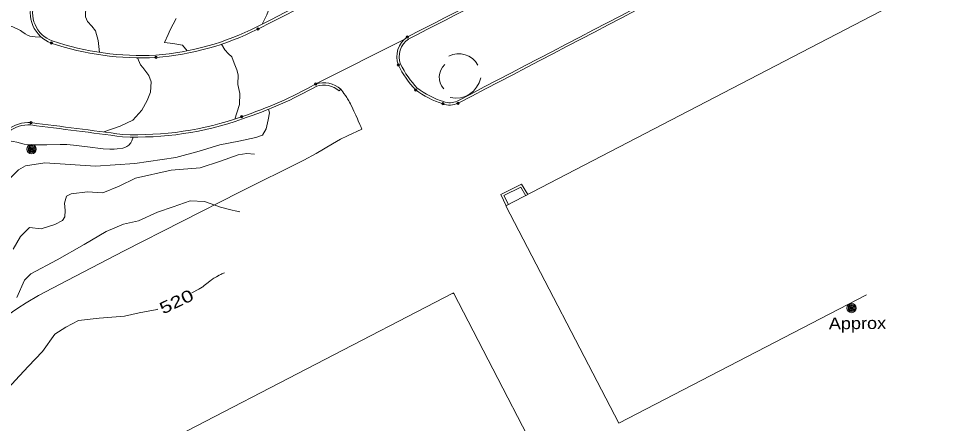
# Model space of a CAD drawing. Extents: x 2361284 to 2366480, y 6976556 to 6985346.
# Drawn here: x 2365034.3 to 2365416.7, y 6979380.5 to 6979545.4 of the extents above; entities that cross this region are included whole.
import ezdxf
from ezdxf.enums import TextEntityAlignment as Align

# ---------------------------------------------------------------- set-up
doc = ezdxf.new("R2010")
doc.units = 0
doc.header["$LTSCALE"] = 1.9
doc.header["$PDMODE"] = 32
doc.header["$PDSIZE"] = 0.95
for name, color, linetype, lineweight in [('12', 7, 'Continuous', 13), ('13', 7, 'Continuous', 13), ('16', 7, 'Continuous', 13), ('3', 7, 'Continuous', 13), ('4', 7, 'Continuous', 13), ('7', 7, 'Continuous', 13)]:
    doc.layers.add(name, color=color, linetype=linetype, lineweight=lineweight)

msp = doc.modelspace()

# ---------------------------------------------------------------- linework, layer by layer
at = {"layer": '12'}
for points in [[(2365121.308, 6979576.326), (2365119.928, 6979575.303), (2365111.99, 6979573.897), (2365105.729, 6979571.798), (2365096.755, 6979569.032), (2365089.949, 6979567.538), (2365082.529, 6979564.398), (2365074.493, 6979560.661), (2365070.51, 6979556.862), (2365063.341, 6979553.584), (2365061.642, 6979550.732), (2365061.489, 6979546.204), (2365062.379, 6979544.334), (2365064.177, 6979542.401), (2365065.576, 6979540.435), (2365066.723, 6979536.506), (2365067.199, 6979531.72)], [(2365043.569, 6979537.876), (2365040.968, 6979538.031), (2365038.905, 6979538.365), (2365037.901, 6979538.691), (2365036.887, 6979539.274), (2365035.656, 6979540.226), (2365035.002, 6979540.644), (2365031.989, 6979542.103), (2365030.403, 6979542.72), (2365028.393, 6979543.31), (2365027.374, 6979543.516), (2365025.84, 6979543.707), (2365023.562, 6979543.705), (2365021.562, 6979543.414), (2365020.569, 6979543.173), (2365019.094, 6979542.694), (2365016.941, 6979541.712), (2365014.212, 6979540.026), (2365010.772, 6979537.666), (2365008.98, 6979536.597), (2365003.418, 6979533.731), (2365000.558, 6979532.436)], [(2365118.196, 6979441.849), (2365117.222, 6979441.395), (2365116.743, 6979441.159), (2365116.031, 6979440.794), (2365114.982, 6979440.22), (2365113.95, 6979439.612), (2365113.44, 6979439.294), (2365112.79, 6979438.854), (2365112.368, 6979438.544), (2365111.546, 6979437.894), (2365109.924, 6979436.567), (2365109.372, 6979436.143), (2365109.091, 6979435.939), (2365108.517, 6979435.55), (2365108.222, 6979435.367), (2365107.769, 6979435.11), (2365104.893, 6979433.623)], [(2365090.866, 6979426.919), (2365090.797, 6979426.888), (2365083.489, 6979425.51), (2365077.442, 6979424.101), (2365067.089, 6979423.363), (2365058.669, 6979422.293), (2365053.493, 6979419.673), (2365048.99, 6979416.8), (2365044.078, 6979409.723), (2365038.145, 6979403.617), (2365033.068, 6979398.048), (2365027.257, 6979391.763), (2365022.139, 6979387.334), (2365014.301, 6979381.889), (2365009.957, 6979377.046), (2365004.624, 6979368.746), (2365002.393, 6979364.705), (2364999.96, 6979360.762), (2364997.599, 6979357.698), (2364995.39, 6979356.567), (2364991.199, 6979356.597)]]:
    msp.add_lwpolyline(points, dxfattribs=at)
at = {"layer": '13'}
for points in [[(2365152.005, 6979575.758), (2365150.833, 6979574.887), (2365149.529, 6979572.194), (2365149.399, 6979570.013), (2365148.154, 6979566.352), (2365146.516, 6979561.986), (2365144.395, 6979558.916), (2365138.73, 6979556.151), (2365137.23, 6979552.936), (2365136.695, 6979550.371), (2365135.456, 6979547.079), (2365133.633, 6979543.182)], [(2365098.493, 6979545.5), (2365096.133, 6979540.885), (2365095.231, 6979538.946), (2365093.821, 6979535.773), (2365097.107, 6979535.344), (2365101.064, 6979534.592), (2365102.985, 6979532.33)], [(2365116.96, 6979535.013), (2365118.341, 6979532.746), (2365119.888, 6979531.131), (2365121.18, 6979529.893), (2365122.224, 6979527.283), (2365123.24, 6979524.562), (2365123.819, 6979522.558), (2365123.727, 6979518.586), (2365124.522, 6979514.914), (2365124.295, 6979510.432), (2365123.207, 6979507.011), (2365122.491, 6979504.534)], [(2365082.781, 6979529.488), (2365083.938, 6979526.669), (2365084.959, 6979525.508), (2365087.42, 6979522.271), (2365088.274, 6979519.749), (2365088.124, 6979515.498), (2365086.757, 6979512.024), (2365084.523, 6979508.203), (2365080.903, 6979504.039), (2365075.755, 6979501.66), (2365068.998, 6979499.245)], [(2365136.183, 6979508.484), (2365136.586, 6979507.058), (2365136.033, 6979504.213), (2365135.218, 6979500.525), (2365133.793, 6979497.911), (2365131.011, 6979497.055), (2365124.137, 6979495.429), (2365116.349, 6979494.055), (2365107.943, 6979491.484), (2365098.369, 6979488.793), (2365081.731, 6979486.335), (2365065.689, 6979485.362), (2365045.006, 6979486.656), (2365037.078, 6979485.43), (2365034.204, 6979483.851), (2365029.694, 6979479.341), (2365027.14, 6979475.546), (2365024.67, 6979472.403), (2365023.426, 6979471.618), (2365020.525, 6979471.793)], [(2365080.978, 6979497.149), (2365080.476, 6979495.604), (2365080.07, 6979494.86), (2365079.172, 6979493.838), (2365078.451, 6979493.323), (2365077.929, 6979493.054), (2365076.81, 6979492.699), (2365074.425, 6979492.327), (2365073.23, 6979492.224), (2365071.438, 6979492.176), (2365068.763, 6979492.353), (2365062.355, 6979493.172), (2365056.73, 6979493.923), (2365053.905, 6979494.142), (2365051.202, 6979494.17), (2365045.795, 6979494.064), (2365038.767, 6979493.948), (2365038.014, 6979493.995), (2365036.527, 6979494.244), (2365033.583, 6979495.021), (2365032.103, 6979495.354), (2365027.334, 6979496.179)], [(2365130.427, 6979490.178), (2365127.365, 6979490.429), (2365123.81, 6979489.885), (2365116.552, 6979487.396), (2365108.369, 6979484.608), (2365096.548, 6979483.605), (2365081.958, 6979480.368), (2365075.227, 6979477.203), (2365068.583, 6979474.45), (2365062.439, 6979474.852), (2365055.697, 6979474.028), (2365053.866, 6979473.03), (2365052.983, 6979470.202), (2365053.262, 6979467.203), (2365053.177, 6979464.572), (2365052.161, 6979463.206), (2365049.034, 6979461.553), (2365043.482, 6979459.74), (2365038.727, 6979460.265), (2365035.091, 6979456.62), (2365032.12, 6979451.492)], [(2365124.491, 6979466.63), (2365122.587, 6979467.102), (2365121.334, 6979467.41), (2365116.612, 6979468.516), (2365110.029, 6979470.914), (2365104.236, 6979471.139), (2365097.33, 6979468.722), (2365090.96, 6979466.502), (2365083.193, 6979462.938), (2365077.096, 6979461.58), (2365069.933, 6979458.691), (2365060.984, 6979453.307), (2365050.022, 6979447.081), (2365039.266, 6979441.409), (2365036.668, 6979438.747), (2365033.508, 6979431.714)]]:
    msp.add_lwpolyline(points, dxfattribs=at)
at = {"layer": '16'}
for centre, radius, start, end in [((2365213.838, 6979522.424), 8.721, 28.11827, 118.11827), ((2365212.795, 6979521.562), 6.97, 132.27574, 222.27574), ((2365212.504, 6979523.488), 10.46, 257.76462, 347.76462)]:
    msp.add_arc(centre, radius, start, end, dxfattribs=at)
at = {"layer": '3'}
for p, q in [((2365131.46, 6979542.083), (2365131.458, 6979542.082)), ((2365047.95, 6979536.406), (2365047.93, 6979536.413)), ((2365155.446, 6979518.818), (2365191.575, 6979537.003)), ((2365193.204, 6979537.089), (2365193.301, 6979537.147)), ((2365090.267, 6979530.608), (2365090.246, 6979530.607)), ((2365190.06, 6979526.875), (2365190.025, 6979526.955)), ((2365155.733, 6979517.902), (2365155.915, 6979517.98)), ((2365165.687, 6979516.705), (2365165.064, 6979515.979)), ((2365196.862, 6979517.081), (2365196.736, 6979517.194)), ((2365213.12, 6979511.851), (2365213.081, 6979511.831)), ((2365207.584, 6979511.636), (2365207.626, 6979511.622)), ((2365125.545, 6979504.559), (2365125.562, 6979504.565)), ((2365039.209, 6979502.111), (2365039.261, 6979502.106)), ((2365076.696, 6979497.269), (2365076.613, 6979497.277)), ((2365076.738, 6979498.229), (2365076.738, 6979498.228))]:
    msp.add_line(p, q, dxfattribs=at)
for points in [[(2365174.243, 6979500.326), (2365173.789, 6979501.512), (2365173.474, 6979502.297), (2365172.818, 6979503.853), (2365172.478, 6979504.626), (2365171.778, 6979506.164), (2365171.056, 6979507.693), (2365170.564, 6979508.71), (2365169.564, 6979510.742), (2365169.201, 6979511.446), (2365168.948, 6979511.906), (2365168.417, 6979512.808), (2365168.141, 6979513.251), (2365167.566, 6979514.126), (2365166.963, 6979514.989), (2365166.548, 6979515.561), (2365165.687, 6979516.705)], [(2365027.381, 6979422.865), (2365033.957, 6979427.349), (2365037.3, 6979429.496), (2365042.451, 6979432.489), (2365054.047, 6979438.654), (2365077.349, 6979450.752), (2365124.324, 6979474.72), (2365150.592, 6979487.69), (2365155.633, 6979490.467), (2365162.234, 6979494.395), (2365165.591, 6979496.264), (2365168.435, 6979497.7), (2365174.243, 6979500.326)], [(2365241.949, 6979473.748), (2365239.419, 6979477.985), (2365230.939, 6979473.794), (2365233.183, 6979469.184)], [(2365241.124, 6979473.261), (2365239.051, 6979476.731), (2365232.223, 6979473.356), (2365234.049, 6979469.603)]]:
    msp.add_lwpolyline(points, dxfattribs=at)
for centre, radius, start, end in [((2362239.81, 6985246.954), 6395.873, 296.87924, 298.72114), ((2362239.81, 6985246.954), 6396.833, 296.87924, 298.72114), ((2352739.774, 7003491.687), 27029.926, 297.48154, 297.90714), ((2352739.774, 7003491.687), 27030.886, 297.48154, 297.90714), ((2355215.381, 6999015.249), 21884.095, 297.12411, 297.48186), ((2355215.381, 6999015.248), 21885.055, 297.12411, 297.48186), ((2365052.083, 6979547.764), 13.047, 156.32244, 250.00279), ((2365052.083, 6979547.764), 12.087, 156.32244, 250.00279), ((2365081.847, 6979640.513), 110.227, 274.37023, 296.74983), ((2365081.847, 6979640.513), 111.187, 274.37023, 296.74983), ((2365084.144, 6979643.24), 113.758, 251.2736, 273.11213), ((2365084.144, 6979643.24), 112.798, 251.2736, 273.11213), ((2365198.106, 6979529.984), 9.585, 123.85297, 201.12604), ((2365198.106, 6979529.984), 8.625, 123.85297, 201.12604), ((2365226.965, 6979545.229), 42.173, 206.32224, 223.07883), ((2365226.965, 6979545.229), 41.213, 206.32223, 223.07883), ((2365069.97, 6979671.391), 174.884, 288.42379, 299.25883), ((2365069.97, 6979671.391), 175.845, 288.4238, 299.25883), ((2365158.667, 6979508.554), 10.758, 49.26394, 107.41953), ((2365158.667, 6979508.554), 9.798, 49.26395, 107.41954), ((2365218.513, 6979546.335), 37.339, 233.2297, 252.51837), ((2365218.513, 6979546.335), 36.379, 233.22969, 252.51837), ((2365210.097, 6979518.371), 7.187, 249.89048, 294.87497), ((2365210.097, 6979518.371), 8.147, 249.89048, 294.87497), ((2365082.368, 6979626.578), 129.433, 267.48831, 289.49466), ((2365082.368, 6979626.578), 128.472, 267.48831, 289.49466), ((2365038.33, 6979489.03), 14.069, 85.92585, 169.25954), ((2365038.33, 6979489.03), 13.109, 85.92585, 169.25954), ((2363839.649, 6970073.29), 9504.82, 82.52228, 82.74963), ((2363839.649, 6970073.29), 9505.78, 82.52228, 82.74963)]:
    msp.add_arc(centre, radius, start, end, dxfattribs=at)
for p in [(2365131.892, 6979541.225), (2365047.622, 6979535.504), (2365192.766, 6979537.944), (2365090.32, 6979529.649), (2365189.165, 6979526.529), (2365155.446, 6979518.818), (2365196.161, 6979516.425), (2365207.296, 6979510.721), (2365213.524, 6979510.98), (2365125.241, 6979505.47), (2365039.33, 6979503.063)]:
    msp.add_point(p, dxfattribs=at)
at = {"layer": '4'}
for centre, radius in [((2365039.583, 6979492.235), 1.9), ((2365039.583, 6979492.235), 1.442), ((2365039.583, 6979492.235), 0.539), ((2365039.583, 6979492.235), 0.192), ((2365373.997, 6979427.452), 1.9), ((2365373.997, 6979427.452), 1.442), ((2365373.997, 6979427.452), 0.539), ((2365373.997, 6979427.452), 0.192)]:
    msp.add_circle(centre, radius, dxfattribs=at)
for centre, start, end in [((2365039.583, 6979492.235), 152.21535, 163.46538), ((2365039.583, 6979492.235), 140.96646, 152.21649), ((2365039.583, 6979492.235), 129.71376, 140.96379), ((2365039.583, 6979492.235), 118.46406, 129.71409), ((2365039.583, 6979492.235), 107.21593, 118.46597), ((2365039.583, 6979492.235), 95.96582, 107.21585), ((2365039.583, 6979492.235), 84.71553, 95.96557), ((2365039.583, 6979492.235), 73.46552, 84.71555), ((2365039.583, 6979492.235), 62.21535, 73.46538), ((2365039.583, 6979492.235), 50.96397, 62.214), ((2365039.583, 6979492.235), 39.71588, 50.96591), ((2365039.583, 6979492.235), 28.46656, 39.7166), ((2365039.583, 6979492.235), 17.21479, 28.46483), ((2365039.583, 6979492.235), 174.71552, 185.96556), ((2365039.583, 6979492.235), 163.46611, 174.71615), ((2365039.583, 6979492.235), 185.96287, 197.21291), ((2365039.583, 6979492.235), 197.21479, 208.46483), ((2365039.583, 6979492.235), 208.46822, 219.71826), ((2365039.583, 6979492.235), 219.71376, 230.96379), ((2365039.583, 6979492.235), 230.96397, 242.214), ((2365039.583, 6979492.235), 242.21812, 253.46815), ((2365039.583, 6979492.235), 253.46258, 264.71261), ((2365039.583, 6979492.235), 264.71553, 275.96557), ((2365039.583, 6979492.235), 275.96582, 287.21585), ((2365039.583, 6979492.235), 287.21593, 298.46597), ((2365039.583, 6979492.235), 298.46406, 309.71409), ((2365039.583, 6979492.235), 309.71589, 320.96592), ((2365039.583, 6979492.235), 320.96646, 332.21649), ((2365039.583, 6979492.235), 332.21419, 343.46422), ((2365039.583, 6979492.235), 5.96345, 17.21348), ((2365039.583, 6979492.235), 343.46611, 354.71615), ((2365039.583, 6979492.235), 354.71553, 5.96557), ((2365373.997, 6979427.452), 163.46611, 174.71615), ((2365373.997, 6979427.452), 152.21535, 163.46538), ((2365373.997, 6979427.452), 140.96646, 152.21649), ((2365373.997, 6979427.452), 129.71376, 140.96379), ((2365373.997, 6979427.452), 118.46406, 129.71409), ((2365373.997, 6979427.452), 107.21593, 118.46597), ((2365373.997, 6979427.452), 95.96582, 107.21585), ((2365373.997, 6979427.452), 84.71553, 95.96557), ((2365373.997, 6979427.452), 73.46552, 84.71555), ((2365373.997, 6979427.452), 62.21535, 73.46538), ((2365373.997, 6979427.452), 50.96397, 62.214), ((2365373.997, 6979427.452), 39.71588, 50.96591), ((2365373.997, 6979427.452), 28.46656, 39.7166), ((2365373.997, 6979427.452), 17.21479, 28.46483), ((2365373.997, 6979427.452), 5.96345, 17.21348), ((2365373.997, 6979427.452), 174.71552, 185.96556), ((2365373.997, 6979427.452), 185.96287, 197.21291), ((2365373.997, 6979427.452), 197.21479, 208.46483), ((2365373.997, 6979427.452), 208.46822, 219.71826), ((2365373.997, 6979427.452), 219.71376, 230.96379), ((2365373.997, 6979427.452), 230.96397, 242.214), ((2365373.997, 6979427.452), 242.21812, 253.46815), ((2365373.997, 6979427.452), 253.46258, 264.71261), ((2365373.997, 6979427.452), 264.71553, 275.96557), ((2365373.997, 6979427.452), 275.96582, 287.21585), ((2365373.997, 6979427.452), 287.21593, 298.46597), ((2365373.997, 6979427.452), 298.46406, 309.71409), ((2365373.997, 6979427.452), 309.71589, 320.96592), ((2365373.997, 6979427.452), 320.96646, 332.21649), ((2365373.997, 6979427.452), 332.21419, 343.46422), ((2365373.997, 6979427.452), 343.46611, 354.71615), ((2365373.997, 6979427.452), 354.71553, 5.96557)]:
    msp.add_arc(centre, 0.973, start, end, dxfattribs=at)
at = {"layer": '7', "lineweight": 25}
msp.add_line((2365211.414, 6979433.455), (2365211.764, 6979433.455), dxfattribs=at)
at = {"layer": '7'}
msp.add_lwpolyline([(2365416.672, 6979550.223), (2365410.485, 6979561.396), (2365233.024, 6979469.102), (2365278.998, 6979380.465), (2365380.036, 6979432.839)], dxfattribs=at)
msp.add_lwpolyline([(2365259.919, 6979340.362), (2365211.69, 6979433.598), (2365043.14, 6979346.41), (2365091.368, 6979253.175)], close=True, dxfattribs=at)

# ---------------------------------------------------------------- texts
at = {"layer": '12', "width": 1.35}
msp.add_text(' 520 ', height=4.8, rotation=25.438, dxfattribs=at).set_placement((2365099.687, 6979427.874), align=Align.CENTER)
at = {"layer": '4', "width": 1.15}
msp.add_text('Approx', height=4.799, rotation=0.545, dxfattribs=at).set_placement((2365364.709, 6979418.742))

doc.saveas('drawing.dxf')
